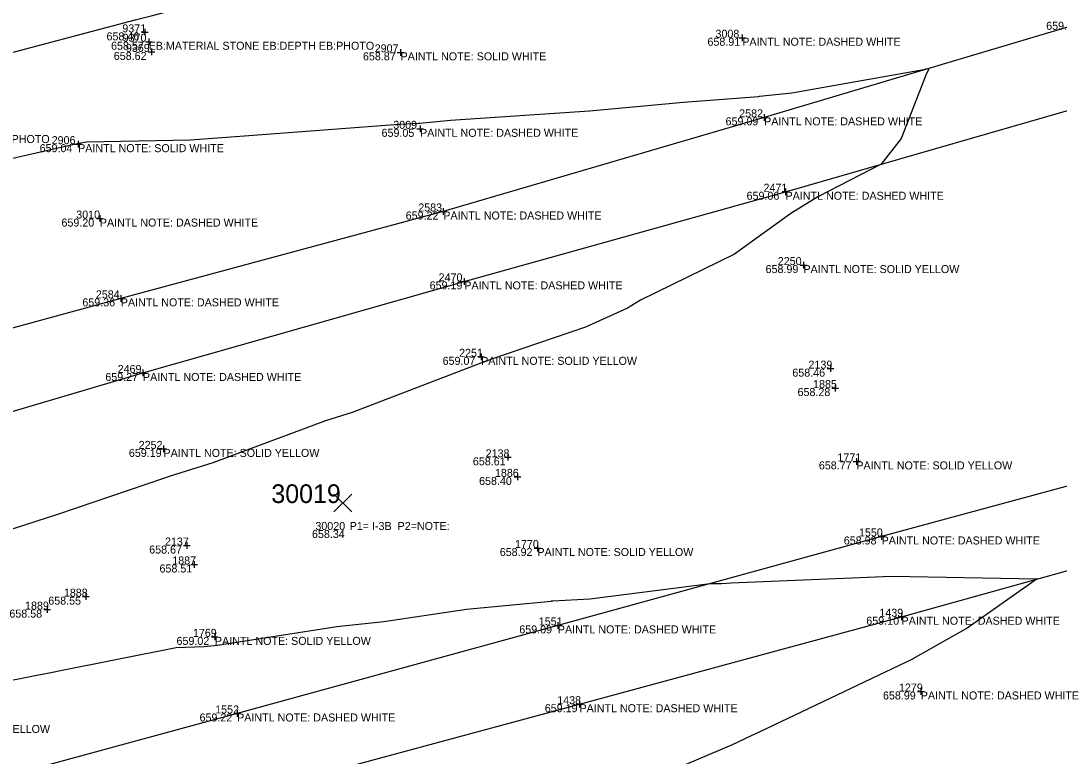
# Model space of a CAD drawing. Extents: x 2129350 to 2137777, y 657588 to 659885.
# Drawn here: x 2134886.7 to 2135042.3, y 659166.7 to 659276.9 of the extents above; entities that cross this region are included whole.
import ezdxf

# ---------------------------------------------------------------- set-up
doc = ezdxf.new("R2010")
doc.units = 0
for name, color, linetype in [('DT_X_Contour_Minor', 7, 'Continuous'), ('GK_Visualization', 7, 'Continuous'), ('PV_X_COP', 7, 'Continuous'), ('SV_X_Shot_Marker', 7, 'Continuous'), ('SV_X_Text_Comment', 7, 'Continuous'), ('SV_X_Text_Description', 7, 'Continuous'), ('SV_X_Text_Elevation', 7, 'Continuous'), ('SV_X_Text_Name', 7, 'Continuous')]:
    doc.layers.add(name, color=color, linetype=linetype)

msp = doc.modelspace()

# ---------------------------------------------------------------- linework, layer by layer
at = {"layer": 'DT_X_Contour_Minor'}
for points in [[(2134881.56, 659271.1), (2134903.85, 659277.01), (2134903.92, 659277.03), (2134904.63, 659277.22), (2134906.24, 659277.61), (2134928.83, 659283.53), (2134930.22, 659283.87), (2134953.03, 659289.84), (2134953.16, 659289.87), (2134955.58, 659290.51), (2134956.73, 659290.81), (2134979.78, 659296.85), (2134980.63, 659297.07), (2135003.97, 659303.18), (2135004.01, 659303.19), (2135005.68, 659303.63), (2135006.2, 659303.76), (2135029.92, 659309.8), (2135030.07, 659309.84), (2135040.21, 659312.42), (2135042.46, 659312.51)], [(2134872.7, 659253.37), (2134895.12, 659258.47), (2134895.39, 659258.53), (2134896.54, 659258.74), (2134912.15, 659259.01), (2134920.86, 659259.67), (2134942.69, 659261.32), (2134946.29, 659261.52), (2134946.47, 659261.54), (2134946.49, 659261.54), (2134951.08, 659261.96), (2134971.91, 659263.37), (2134986, 659264.67), (2134997.23, 659265.54), (2134997.4, 659265.56), (2135002.24, 659266.07), (2135022.26, 659269.64), (2135022.34, 659269.65), (2135022.73, 659269.73), (2135022.7, 659269.52), (2135022.43, 659268.98), (2135018.62, 659259.24), (2135015.65, 659255.38), (2135006.12, 659250.49), (2135002.1, 659247.99), (2134993.66, 659241.91), (2134979.55, 659234.99), (2134977.6, 659233.8), (2134971.31, 659230.96), (2134957.21, 659226.16), (2134956.1, 659225.73), (2134955.9, 659225.66), (2134936.35, 659218.19), (2134932.38, 659216.94), (2134915.46, 659210.61), (2134909.07, 659208.61), (2134908.07, 659208.29), (2134892.21, 659202.86), (2134883.98, 659200.25)], [(2134869.43, 659174.92), (2134889.08, 659178.81), (2134890.69, 659179.1), (2134891.67, 659179.32), (2134892.37, 659179.47), (2134909.97, 659182.94), (2134914.15, 659183.11), (2134916.15, 659183.3), (2134934.06, 659186.1), (2134941.08, 659186.87), (2134953.49, 659188.7), (2134966.17, 659189.91), (2134966.22, 659189.92), (2134966.44, 659189.94), (2134971.95, 659190.23), (2134989.98, 659192.52), (2134991.69, 659192.55), (2134993.16, 659192.65), (2135017.17, 659193.63), (2135017.18, 659193.63), (2135017.18, 659193.63), (2135039.03, 659193.22), (2135028.5, 659185.87), (2135020.37, 659181.26), (2135020.36, 659181.25), (2135020.31, 659181.22), (2135013.19, 659177.8), (2134997.33, 659170.27), (2134996.27, 659169.76), (2134993.19, 659168.31), (2134974.37, 659160.31)]]:
    msp.add_lwpolyline(points, dxfattribs=at)
at = {"layer": 'GK_Visualization'}
for p, q in [((2134933.61, 659203.27), (2134936.28, 659205.94)), ((2134933.61, 659205.94), (2134936.28, 659203.27))]:
    msp.add_line(p, q, dxfattribs=at)
at = {"layer": 'PV_X_COP'}
for points in [[(2134520.09, 659114.68), (2134568.13, 659128.65), (2134617.04, 659142.36), (2134664.66, 659155.43), (2134712.28, 659169.02), (2134760.57, 659182.99), (2134808.9, 659196.44), (2134857.18, 659209.96), (2134905, 659224.09), (2134953.16, 659237.82), (2135001.3, 659251.25), (2135048.97, 659264.98), (2135097.44, 659279.39), (2135145, 659292.73), (2135193.91, 659307.04), (2135241.76, 659320.98), (2135289.6, 659334.84), (2135337.5, 659347.93), (2135385.12, 659361.55), (2135434.03, 659374.73), (2135482.21, 659388.12), (2135530.34, 659401.09)], [(2134536.41, 659055.93), (2134584.63, 659068.49), (2134632.85, 659082.56), (2134681.18, 659095.41), (2134729.3, 659108.49), (2134777.5, 659121.73), (2134825.62, 659134.79), (2134874.04, 659148.15), (2134922.3, 659161.49), (2134970.42, 659174.45), (2135018.69, 659187.56), (2135066.93, 659200.99), (2135115.08, 659213.86), (2135163, 659227.16), (2135211.7, 659240.81), (2135259.71, 659253.66), (2135307.87, 659266.85), (2135356.61, 659279.29), (2135404.78, 659292.12), (2135453.04, 659304.51), (2135501.4, 659316.76), (2135549.86, 659329.4)], [(2135046.23, 659276.72), (2134998.09, 659262.4), (2134950.01, 659248.29), (2134901.68, 659235.27), (2134853.4, 659222.06), (2134806.14, 659207.81), (2134757.33, 659193.63), (2134709.1, 659180.43), (2134661.25, 659167.25), (2134613.17, 659153.43), (2134564.8, 659140.1), (2134516.96, 659126.54), (2134468.46, 659112.97), (2134420.69, 659099.3), (2134372.8, 659086.61), (2134323.79, 659072.7)], [(2135063.97, 659212.65), (2135015.7, 659199.59), (2134967.18, 659186.26), (2134919.11, 659173.06), (2134870.79, 659159.93), (2134822.4, 659146.6), (2134774.18, 659133.37), (2134726.37, 659119.97), (2134677.87, 659106.94), (2134629.67, 659093.61), (2134581.23, 659080.17), (2134532.94, 659067.73), (2134484.94, 659054.04), (2134437, 659040.07), (2134388.52, 659027.39), (2134340.25, 659013.73)]]:
    msp.add_lwpolyline(points, dxfattribs=at)
at = {"layer": 'SV_X_Shot_Marker'}
for p, q in [((2134904.76, 659275.14), (2134905.76, 659275.14)), ((2134905.26, 659275.64), (2134905.26, 659274.64)), ((2134905.26, 659275.14), (2134905.26, 659275.14)), ((2134905.86, 659274.23), (2134905.86, 659273.23)), ((2134994.32, 659274.33), (2134995.32, 659274.33)), ((2134994.82, 659274.83), (2134994.82, 659273.83)), ((2134994.82, 659274.33), (2134994.82, 659274.33)), ((2134905.36, 659273.73), (2134906.36, 659273.73)), ((2134905.86, 659273.73), (2134905.86, 659273.73)), ((2134906.28, 659272.7), (2134906.28, 659271.7)), ((2134943.61, 659272.64), (2134943.61, 659271.64)), ((2134905.78, 659272.2), (2134906.78, 659272.2)), ((2134906.28, 659272.2), (2134906.28, 659272.2)), ((2134943.11, 659272.14), (2134944.11, 659272.14)), ((2134943.61, 659272.14), (2134943.61, 659272.14)), ((2134997.59, 659262.4), (2134998.59, 659262.4)), ((2134998.09, 659262.9), (2134998.09, 659261.9)), ((2134998.09, 659262.4), (2134998.09, 659262.4)), ((2134946.03, 659260.68), (2134947.03, 659260.68)), ((2134946.53, 659261.18), (2134946.53, 659260.18)), ((2134946.53, 659260.68), (2134946.53, 659260.68)), ((2134895.28, 659258.88), (2134895.28, 659257.88)), ((2134894.78, 659258.38), (2134895.78, 659258.38)), ((2134895.28, 659258.38), (2134895.28, 659258.38)), ((2135000.8, 659251.25), (2135001.8, 659251.25)), ((2135001.3, 659251.75), (2135001.3, 659250.75)), ((2135001.3, 659251.25), (2135001.3, 659251.25)), ((2134898.54, 659247.73), (2134898.54, 659246.73)), ((2134949.51, 659248.29), (2134950.51, 659248.29)), ((2134950.01, 659248.79), (2134950.01, 659247.79)), ((2134950.01, 659248.29), (2134950.01, 659248.29)), ((2134898.04, 659247.23), (2134899.04, 659247.23)), ((2134898.54, 659247.23), (2134898.54, 659247.23)), ((2135003.48, 659240.26), (2135004.48, 659240.26)), ((2135003.98, 659240.76), (2135003.98, 659239.76)), ((2135003.98, 659240.26), (2135003.98, 659240.26)), ((2134952.66, 659237.82), (2134953.66, 659237.82)), ((2134953.16, 659238.32), (2134953.16, 659237.32)), ((2134953.16, 659237.82), (2134953.16, 659237.82)), ((2134901.18, 659235.27), (2134902.18, 659235.27)), ((2134901.68, 659235.77), (2134901.68, 659234.77)), ((2134901.68, 659235.27), (2134901.68, 659235.27)), ((2134955.18, 659226.51), (2134956.18, 659226.51)), ((2134955.68, 659227.01), (2134955.68, 659226.01)), ((2134955.68, 659226.51), (2134955.68, 659226.51)), ((2134905, 659224.59), (2134905, 659223.59)), ((2135007.55, 659224.74), (2135008.55, 659224.74)), ((2135008.05, 659225.24), (2135008.05, 659224.24)), ((2135008.05, 659224.74), (2135008.05, 659224.74)), ((2134904.5, 659224.09), (2134905.5, 659224.09)), ((2134905, 659224.09), (2134905, 659224.09)), ((2135008.23, 659221.83), (2135009.23, 659221.83)), ((2135008.73, 659222.33), (2135008.73, 659221.33)), ((2135008.73, 659221.83), (2135008.73, 659221.83)), ((2134907.58, 659212.71), (2134908.58, 659212.71)), ((2134908.08, 659213.21), (2134908.08, 659212.21)), ((2134908.08, 659212.71), (2134908.08, 659212.71)), ((2134959.67, 659211.95), (2134959.67, 659210.95)), ((2134959.17, 659211.45), (2134960.17, 659211.45)), ((2134959.67, 659211.45), (2134959.67, 659211.45)), ((2135011.41, 659210.84), (2135012.41, 659210.84)), ((2135011.91, 659211.34), (2135011.91, 659210.34)), ((2135011.91, 659210.84), (2135011.91, 659210.84)), ((2134961.12, 659209.02), (2134961.12, 659208.02)), ((2134960.62, 659208.52), (2134961.62, 659208.52)), ((2134961.12, 659208.52), (2134961.12, 659208.52)), ((2135015.2, 659199.59), (2135016.2, 659199.59)), ((2135015.7, 659200.09), (2135015.7, 659199.09)), ((2135015.7, 659199.59), (2135015.7, 659199.59)), ((2134911.09, 659198.23), (2134912.09, 659198.23)), ((2134911.59, 659198.73), (2134911.59, 659197.73)), ((2134911.59, 659198.23), (2134911.59, 659198.23)), ((2134964.12, 659198.36), (2134964.12, 659197.36)), ((2134963.62, 659197.86), (2134964.62, 659197.86)), ((2134964.12, 659197.86), (2134964.12, 659197.86)), ((2134912.19, 659195.39), (2134913.19, 659195.39)), ((2134912.69, 659195.89), (2134912.69, 659194.89)), ((2134912.69, 659195.39), (2134912.69, 659195.39)), ((2134895.96, 659190.57), (2134896.96, 659190.57)), ((2134896.46, 659191.07), (2134896.46, 659190.07)), ((2134896.46, 659190.57), (2134896.46, 659190.57)), ((2134890.13, 659188.63), (2134891.13, 659188.63)), ((2134890.63, 659189.13), (2134890.63, 659188.13)), ((2134890.63, 659188.63), (2134890.63, 659188.63)), ((2135018.19, 659187.56), (2135019.19, 659187.56)), ((2135018.69, 659188.06), (2135018.69, 659187.06)), ((2135018.69, 659187.56), (2135018.69, 659187.56)), ((2134966.68, 659186.26), (2134967.68, 659186.26)), ((2134967.18, 659186.76), (2134967.18, 659185.76)), ((2134967.18, 659186.26), (2134967.18, 659186.26)), ((2134915.29, 659184.54), (2134916.29, 659184.54)), ((2134915.79, 659185.04), (2134915.79, 659184.04)), ((2134915.79, 659184.54), (2134915.79, 659184.54)), ((2135021.07, 659176.35), (2135022.07, 659176.35)), ((2135021.57, 659176.85), (2135021.57, 659175.85)), ((2135021.57, 659176.35), (2135021.57, 659176.35)), ((2134970.42, 659174.95), (2134970.42, 659173.95)), ((2134918.61, 659173.06), (2134919.61, 659173.06)), ((2134919.11, 659173.56), (2134919.11, 659172.56)), ((2134919.11, 659173.06), (2134919.11, 659173.06)), ((2134969.92, 659174.45), (2134970.92, 659174.45)), ((2134970.42, 659174.45), (2134970.42, 659174.45))]:
    msp.add_line(p, q, dxfattribs=at)

# ---------------------------------------------------------------- texts
at = {"layer": 'GK_Visualization'}
msp.add_text('30019', height=2.8, dxfattribs=at).set_placement((2134924.24, 659204.6))
at = {"layer": 'SV_X_Text_Comment'}
for s, p in [('PAINTL NOTE: DASHED WHITE', (2134994.82, 659273.13)), ('EB:MATERIAL STONE EB:DEPTH EB:PHOTO', (2134905.86, 659272.53)), ('PAINTL NOTE: SOLID WHITE', (2134943.61, 659270.94)), ('PAINTL NOTE: DASHED WHITE', (2134998.09, 659261.2)), ('PAINTL NOTE: DASHED WHITE', (2134946.53, 659259.48)), ('EB:MATERIAL STONE EB:DEPTH EB:PHOTO', (2134857.23, 659258.55)), ('PAINTL NOTE: SOLID WHITE', (2134895.28, 659257.18)), ('PAINTL NOTE: DASHED WHITE', (2135001.3, 659250.05)), ('PAINTL NOTE: DASHED WHITE', (2134950.01, 659247.09)), ('PAINTL NOTE: DASHED WHITE', (2134898.54, 659246.03)), ('PAINTL NOTE: SOLID YELLOW', (2135003.98, 659239.06)), ('PAINTL NOTE: DASHED WHITE', (2134953.16, 659236.62)), ('PAINTL NOTE: DASHED WHITE', (2134901.68, 659234.07)), ('PAINTL NOTE: SOLID YELLOW', (2134955.68, 659225.31)), ('PAINTL NOTE: DASHED WHITE', (2134905, 659222.89)), ('PAINTL NOTE: SOLID YELLOW', (2134908.08, 659211.51)), ('PAINTL NOTE: SOLID YELLOW', (2135011.91, 659209.64)), ('PAINTL NOTE: DASHED WHITE', (2135015.7, 659198.39)), ('PAINTL NOTE: SOLID YELLOW', (2134964.12, 659196.66)), ('PAINTL NOTE: DASHED WHITE', (2135018.69, 659186.36)), ('PAINTL NOTE: DASHED WHITE', (2134967.18, 659185.06)), ('PAINTL NOTE: SOLID YELLOW', (2134915.79, 659183.34)), ('PAINTL NOTE: DASHED WHITE', (2135021.57, 659175.16)), ('PAINTL NOTE: DASHED WHITE', (2134919.11, 659171.86)), ('PAINTL NOTE: DASHED WHITE', (2134970.42, 659173.25)), ('PAINTL NOTE: SOLID YELLOW', (2134867.71, 659170.14))]:
    msp.add_text(s, height=1.2, dxfattribs=at).set_placement(p)
at = {"layer": 'SV_X_Text_Description'}
msp.add_text('P1= I-3B  P2=NOTE:', height=1.2, dxfattribs=at).set_placement((2134935.98, 659200.56))
at = {"layer": 'SV_X_Text_Elevation'}
for s, p in [('659.00', (2135040.36, 659275.52)), ('658.46', (2134899.54, 659273.94)), ('658.91', (2134989.6, 659273.13)), ('658.57', (2134900.22, 659272.53)), ('658.62', (2134900.63, 659271)), ('658.87', (2134937.97, 659270.94)), ('659.09', (2134992.31, 659261.2)), ('659.05', (2134940.76, 659259.48)), ('659.04', (2134889.52, 659257.18)), ('659.06', (2134995.46, 659250.05)), ('659.22', (2134944.38, 659247.09)), ('659.20', (2134892.79, 659246.03)), ('658.99', (2134998.31, 659239.06)), ('659.19', (2134947.96, 659236.62)), ('659.36', (2134895.92, 659234.07)), ('659.07', (2134949.91, 659225.31)), ('658.46', (2135002.32, 659223.54)), ('659.27', (2134899.36, 659222.89)), ('658.28', (2135003.1, 659220.63)), ('659.19', (2134902.89, 659211.51)), ('658.61', (2134954.44, 659210.25)), ('658.77', (2135006.29, 659209.64)), ('658.40', (2134955.37, 659207.31)), ('658.34', (2134930.33, 659199.36)), ('658.98', (2135010.03, 659198.39)), ('658.67', (2134905.94, 659197.03)), ('658.92', (2134958.47, 659196.66)), ('658.51', (2134907.48, 659194.19)), ('658.55', (2134890.81, 659189.37)), ('658.58', (2134884.98, 659187.43)), ('659.10', (2135013.4, 659186.36)), ('659.09', (2134961.4, 659185.06)), ('659.02', (2134910.03, 659183.34)), ('658.99', (2135015.9, 659175.16)), ('659.22', (2134913.48, 659171.86)), ('659.19', (2134965.22, 659173.25))]:
    msp.add_text(s, height=1.2, dxfattribs=at).set_placement(p)
at = {"layer": 'SV_X_Text_Name'}
for s, p in [('9371', (2134901.91, 659275.14)), ('9370', (2134901.96, 659273.73)), ('3008', (2134990.8, 659274.33)), ('9369', (2134902.44, 659272.2)), ('2907', (2134939.73, 659272.14)), ('2582', (2134994.35, 659262.4)), ('3009', (2134942.51, 659260.68)), ('2906', (2134891.32, 659258.38)), ('2471', (2134998, 659251.25)), ('2583', (2134946.26, 659248.29)), ('3010', (2134895, 659247.23)), ('2250', (2135000.14, 659240.26)), ('2470', (2134949.31, 659237.82)), ('2584', (2134897.94, 659235.27)), ('2251', (2134952.38, 659226.51)), ('2139', (2135004.74, 659224.74)), ('2469', (2134901.21, 659224.09)), ('1885', (2135005.43, 659221.83)), ('2252', (2134904.36, 659212.71)), ('2138', (2134956.36, 659211.45)), ('1771', (2135009.08, 659210.84)), ('1886', (2134957.75, 659208.52)), ('30020', (2134930.84, 659200.56)), ('1550', (2135012.3, 659199.59)), ('2137', (2134908.3, 659198.23)), ('1770', (2134960.76, 659197.86)), ('1887', (2134909.39, 659195.39)), ('1888', (2134893.15, 659190.57)), ('1889', (2134887.33, 659188.63)), ('1439', (2135015.36, 659187.56)), ('1551', (2134964.32, 659186.26)), ('1769', (2134912.49, 659184.54)), ('1279', (2135018.3, 659176.35)), ('1438', (2134967.08, 659174.45)), ('1552', (2134915.82, 659173.06))]:
    msp.add_text(s, height=1.2, dxfattribs=at).set_placement(p)

doc.saveas('drawing.dxf')
